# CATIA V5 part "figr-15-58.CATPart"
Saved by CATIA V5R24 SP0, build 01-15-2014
Part number: Part1
Bounding box of the stored display mesh (mm): x -20 to 20, y -25 to 25, z 0 to 50
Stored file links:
  D:\KAVITA\CATIA V5-6R2014 Project_ Kavita\CATIA V5-6R2014_partfiles\Partfiles\c15_catia_v5-6r2014_prt\figr-15-58.CATPart
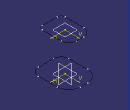
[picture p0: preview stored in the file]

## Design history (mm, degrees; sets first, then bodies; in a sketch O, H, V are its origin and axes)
SheetMetalParameters1: Thickness 2, BendRadius 4, KFactor 0.400515 {= log(min(100,max(20*SheetMetalParameters1.BendRadius,SheetMetalParameters1.Thickness)/SheetMetalParameters1.Thickness))/log(100)/2}, ReliefRadialLength 1, ReliefAxialLength 2, MinimumBendRadius 0
Body1 (main body)
  Plane1: type Offset, RefPlane xy-plane, Offset 50
  Sketch1 on xy-plane, origin (0, 0, 0), H (1, 0, 0), V (0, 1, 0)
    line L1 (20, 10) -> (20, -15)
    line L2 (10, -25) -> (-10, -25)
    line L3 (-20, -15) -> (-20, 10)
    line L4 (-5, 25) -> (5, 25)
    arc A1 centre (5, 10) radius 15 from (20, 10) to (5, 25) ccw
    arc A2 centre (-5, 10) radius 15 from (-20, 10) to (-5, 25) cw
    arc A3 centre (10, -15) radius 10 from (20, -15) to (10, -25) cw
    arc A4 centre (-10, -15) radius 10 from (-10, -25) to (-20, -15) cw
    radius A1 = 15
    radius A2 = 15
    radius A3 = 10
    radius A4 = 10
    distance L4 L2 = 50
    distance L3 L1 = 40
    vertical: L1 V, L3 V
    horizontal: L2 H, L4 H
    equidistance: L1 L3 O, L2 L4 O
    tangency: A1 L1, A1 L4, A2 L3, A2 L4, A3 L1, A3 L2, A4 L2, A4 L3
  Sketch2 on Plane1, origin (0, 0, 50), H (1, 0, 0), V (0, 1, 0)
    line L1 (15, 10) -> (15, -15)
    line L2 (10, -20) -> (-10, -20)
    line L3 (-15, -15) -> (-15, 10)
    line L4 (-5, 20) -> (5, 20)
    arc A1 centre (5, 10) radius 10 from (15, 10) to (5, 20) ccw
    arc A2 centre (10, -15) radius 5 from (15, -15) to (10, -20) cw
    arc A3 centre (-10, -15) radius 5 from (-10, -20) to (-15, -15) cw
    arc A4 centre (-5, 10) radius 10 from (-15, 10) to (-5, 20) cw
    radius A1 = 10
    radius A2 = 5
    radius A3 = 5
    radius A4 = 10
    distance L4 L2 = 40
    distance L1 L3 = 30
    vertical: L1 V, L3 V
    horizontal: L2 H, L4 H
    equidistance: L1 L3 O, L2 L4 O
    tangency: A1 L1, A1 L4, A2 L1, A2 L2, A3 L2, A3 L3, A4 L3, A4 L4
